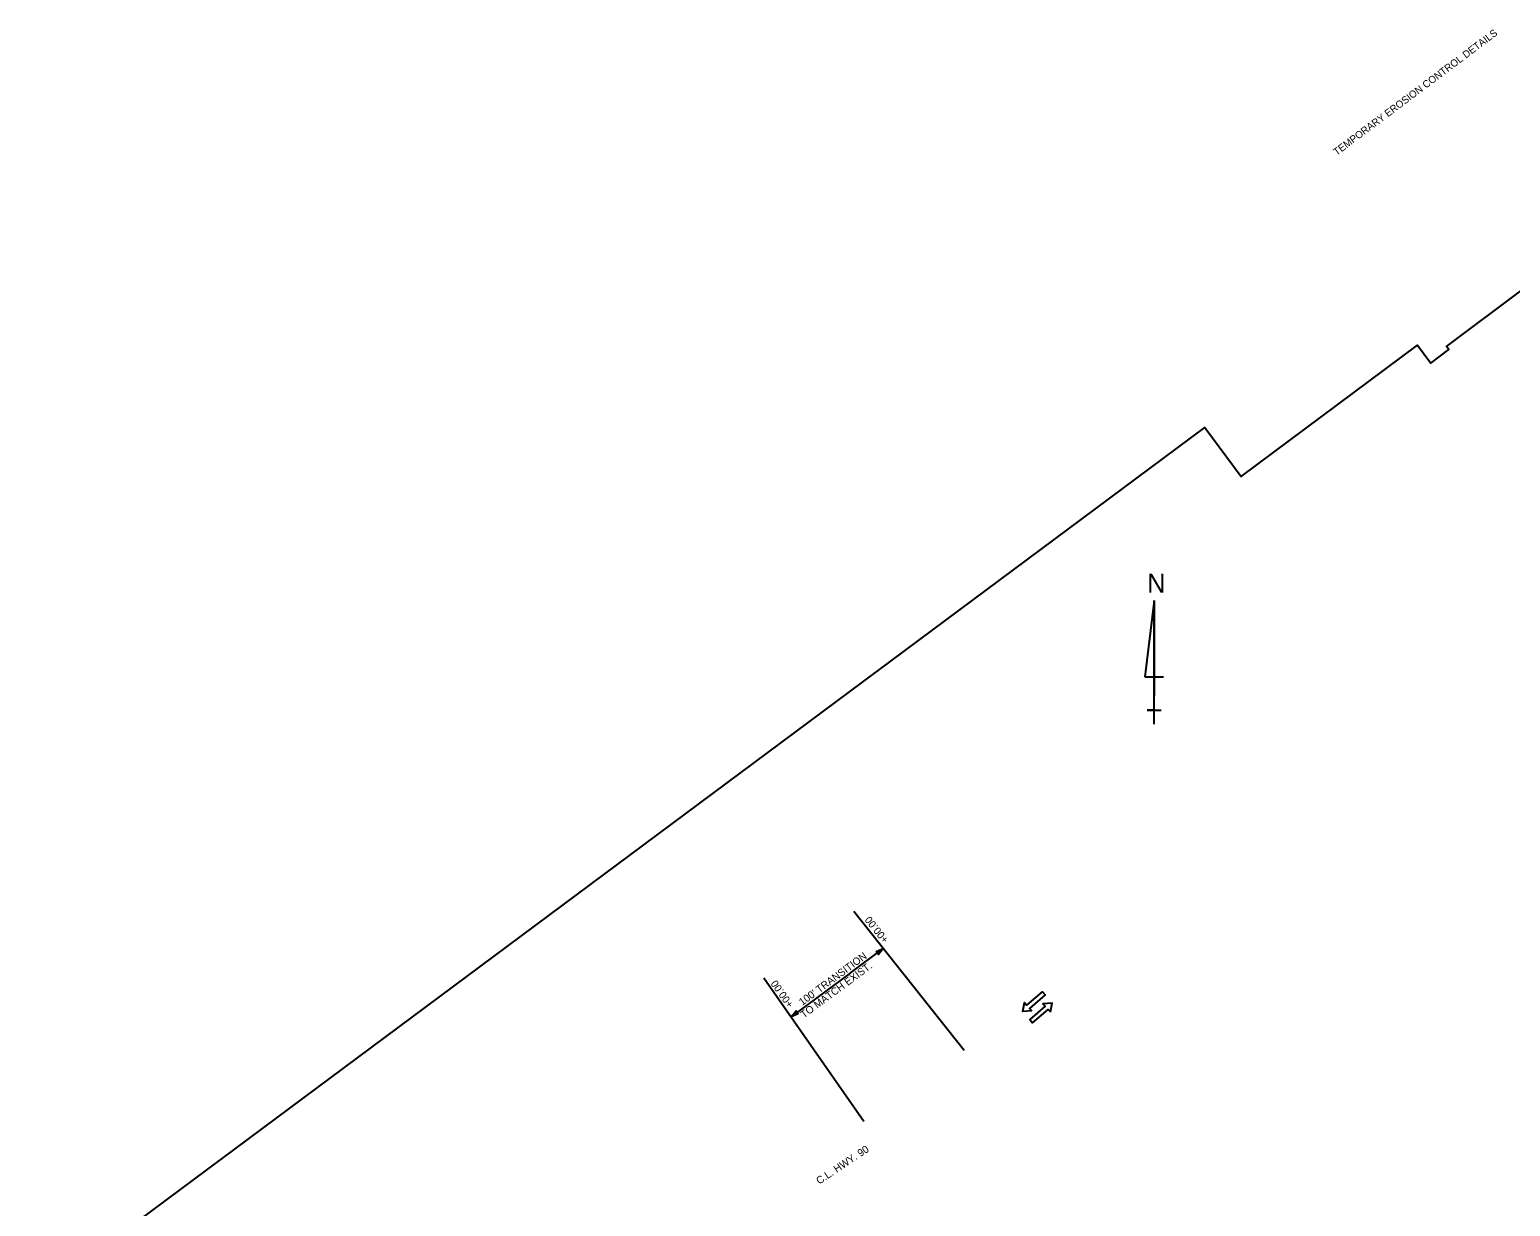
# Model space of a CAD drawing. Extents: x 1571137 to 1573037, y 731597 to 733459.
# Drawn here: x 1571137 to 1572334, y 732507 to 733459 of the extents above; entities that cross this region are included whole.
import ezdxf

# ---------------------------------------------------------------- set-up
doc = ezdxf.new("R2010")
doc.units = 0
for name, color, linetype in [('R_Annotation', 7, 'Continuous'), ('R_Border', 7, 'Continuous'), ('R_Draft', 7, 'Continuous'), ('R_MOT', 7, 'Continuous'), ('R_Proposed Road_Lane', 7, 'Continuous'), ('S_MSC_PT_SYM', 7, 'Continuous')]:
    doc.layers.add(name, color=color, linetype=linetype)

msp = doc.modelspace()

# ---------------------------------------------------------------- linework, layer by layer
at = {"layer": 'R_Draft'}
for p, q in [((1571803, 732746), (1571892.3, 732633.7)), ((1571800.1, 732695.9), (1571826.9, 732715.8)), ((1571730.3, 732692.1), (1571811.3, 732576.3)), ((1571800.2, 732695.9), (1571752.4, 732660.5))]:
    msp.add_line(p, q, dxfattribs=at)
for points in [[(1571821.2, 732713.4), (1571826.9, 732715.8), (1571823, 732711)], [(1571758.2, 732662.9), (1571752.4, 732660.5), (1571756.4, 732665.3)]]:
    msp.add_lwpolyline(points, close=True, dxfattribs=at)
at = {"layer": 'R_MOT'}
for points in [[(1571947, 732665.3), (1571939.7, 732664.8), (1571941.1, 732672.1), (1571943, 732670), (1571955.5, 732680.8), (1571957.7, 732678.3), (1571945.2, 732667.4)], [(1571962, 732664.5), (1571963.4, 732671.7), (1571956, 732671.2), (1571957.9, 732669.1), (1571945.4, 732658.3), (1571947.6, 732655.7), (1571960.1, 732666.6)]]:
    msp.add_lwpolyline(points, close=True, dxfattribs=at)
at = {"layer": 'R_Proposed Road_Lane'}
for p, q in [((1572045.9, 732997.1), (1572038.2, 732935.5)), ((1572045.9, 732897.1), (1572045.9, 732997.1)), ((1572045.9, 732997.1), (1572045.9, 732920.2)), ((1572038.2, 732935.5), (1572053.5, 732935.5)), ((1572045.9, 732897.1), (1572045.9, 732920.2)), ((1572045.9, 732908.6), (1572040.1, 732908.6)), ((1572040.1, 732908.6), (1572051.6, 732908.6)), ((1572045.9, 732897.1), (1572045.9, 732908.6))]:
    msp.add_line(p, q, dxfattribs=at)
at = {"layer": 'S_MSC_PT_SYM'}
msp.add_lwpolyline([(1572536.7, 733221.6), (1573036.7, 732549.8), (1571756.9, 731597.3), (1571137, 732430.2), (1572086.8, 733137.2), (1572116.3, 733097.5), (1572258.8, 733203.6), (1572269.5, 733189.2), (1572284.1, 733200.1), (1572282.1, 733202.7), (1572344.4, 733249.1)], dxfattribs=at)

# ---------------------------------------------------------------- texts
at = {"layer": 'R_Annotation'}
for s, rotation, p in [('+00.00', 128.4772, (1571831.6, 732723.1)), ("100' TRANSITION", 36.5764, (1571761.5, 732669.3)), ('TO MATCH EXIST.', 36.5764, (1571762.8, 732659.1)), ('+00.00', 124.9772, (1571754.7, 732670.6)), ('C.L. HWY. 90', 33.804, (1571775.2, 732524.8))]:
    msp.add_text(s, height=6, rotation=rotation, dxfattribs=at).set_placement(p)
at = {"layer": 'R_Border'}
msp.add_text('TEMPORARY EROSION CONTROL DETAILS', height=5.862, rotation=36.9636, dxfattribs=at).set_placement((1572193.4, 733356.7))
at = {"layer": 'R_Proposed Road_Lane'}
msp.add_text('N', height=15.4, dxfattribs=at).set_placement((1572040.2, 733003.5))

doc.saveas('drawing.dxf')
